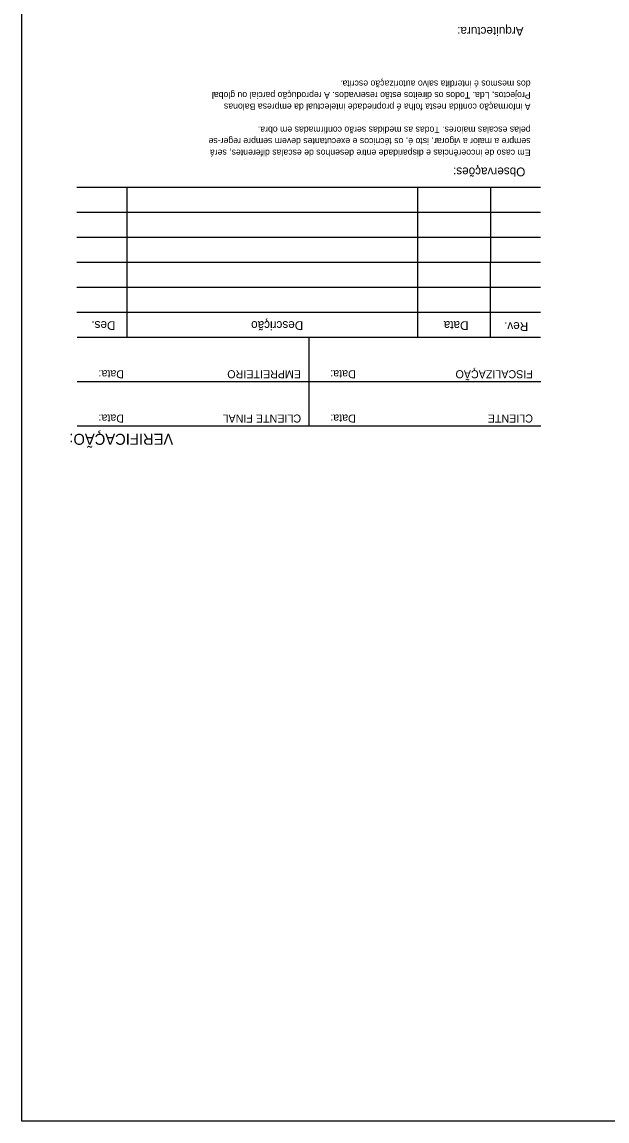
# Model space of a CAD drawing. Extents: x 1290.6 to 1307.2, y -290.6 to -281.7.
# Drawn here: x 1295.594 to 1297.932, y -290.601 to -286.209 of the extents above; entities that cross this region are included whole.
import ezdxf

# ---------------------------------------------------------------- set-up
doc = ezdxf.new("R2010")
doc.units = 0
doc.layers.add('Level 62', color=7, linetype='Continuous')

msp = doc.modelspace()

# ---------------------------------------------------------------- linework, layer by layer
at = {"layer": 'Level 62'}
for p, q in [((1297.66556, -286.87), (1295.81336, -286.87)), ((1296.01336, -286.87), (1296.01336, -287.47)), ((1297.17416, -286.87), (1297.17416, -287.47)), ((1297.46556, -286.87), (1297.46536, -287.47)), ((1297.66556, -286.97), (1295.81336, -286.97)), ((1297.66536, -287.07), (1295.81356, -287.07)), ((1297.66536, -287.17), (1295.81336, -287.17)), ((1297.66556, -287.27), (1295.81336, -287.27)), ((1297.66556, -287.37), (1295.81356, -287.37)), ((1297.66616, -287.47), (1295.81396, -287.47)), ((1296.74012, -287.4701), (1296.74072, -287.8241)), ((1297.66682, -287.6471), (1295.81482, -287.6471)), ((1297.66676, -287.824), (1295.81456, -287.824))]:
    msp.add_line(p, q, dxfattribs=at)
msp.add_lwpolyline([(1307.19356, -282.2006), (1307.19356, -290.6006), (1295.59396, -290.6006), (1295.59396, -282.2006)], close=True, dxfattribs=at)

# ---------------------------------------------------------------- texts
for s, height, rotation, p in [('Arquitectura:', 0.0349944, 179.99997, (1297.59816, -286.2286)), ('dos mesmos é interdita salvo autorização escrita.', 0.0260004, 179.99999, (1297.62636, -286.4428)), ('Projectos, Lda. Todos os direitos estão reservados. A reprodução parcial ou global', 0.0260004, 179.99999, (1297.62636, -286.4888)), ('A informação contida nesta folha é propriedade intelectual da empresa Balonas', 0.0260004, 179.99999, (1297.62636, -286.5348)), ('pelas escalas maiores. Todas as medidas serão confirmadas em obra.', 0.0260004, 179.99999, (1297.62636, -286.6268)), ('sempre a maior a vigorar, isto é, os técnicos e executantes devem sempre reger-se', 0.0260004, 179.99999, (1297.62636, -286.6728)), ('Em caso de incoerências e disparidade entre desenhos de escalas diferentes, será', 0.0260004, 179.99999, (1297.62616, -286.7188)), ('Observações:', 0.0350004, 179.99999, (1297.60516, -286.7904)), ('Descrição', 0.035, 179.99999, (1296.71776, -287.4044)), ('Des.', 0.035, 179.99999, (1295.96736, -287.4044)), ('Data', 0.035, 179.99999, (1297.37816, -287.4044)), ('Rev.', 0.035, 179.99999, (1297.61676, -287.4084)), ('Data:', 0.031994, 179.99997, (1296.00176, -287.6004)), ('EMPREITEIRO', 0.0319944, 179.99997, (1296.70896, -287.6004)), ('Data:', 0.031994, 179.99997, (1296.92776, -287.6004)), ('FISCALIZAÇÃO', 0.0319944, 179.99997, (1297.63536, -287.6004)), ('Data:', 0.031994, 179.99997, (1296.00176, -287.7774)), ('CLIENTE FINAL', 0.0319944, 179.99997, (1296.70936, -287.7774)), ('Data:', 0.031994, 179.99997, (1296.92796, -287.7774)), ('CLIENTE', 0.031994, 179.99997, (1297.63576, -287.7774)), ('VERIFICAÇÃO:', 0.0439968, 179.99997, (1296.19836, -287.8544))]:
    msp.add_text(s, height=height, rotation=rotation, dxfattribs=at).set_placement(p)

doc.saveas('drawing.dxf')
